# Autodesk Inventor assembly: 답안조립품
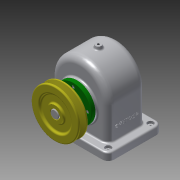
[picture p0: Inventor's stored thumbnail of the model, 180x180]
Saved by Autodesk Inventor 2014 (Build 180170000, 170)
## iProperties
Created: 2016-10
Part Number: 답안조립품
Document SubType Name: Assembly
Designer: USER
Author: USER
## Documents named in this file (15)
- C:\Users\USER\Desktop\461008V1010\답안조립품.iam
- C:\Users\USER\Desktop\461008V1010\V-벨트풀리.ipt
- C:\Users\USER\Desktop\461008V1010\뒤커버.ipt
- C:\Users\USER\Desktop\461008V1010\멈춤나사 - M4x10.ipt
- C:\Users\USER\Desktop\461008V1010\베어링 6203.ipt
- C:\Users\USER\Desktop\461008V1010\본체.ipt
- C:\Users\USER\Desktop\461008V1010\볼트 M3 x 8.ipt
- C:\Users\USER\Desktop\461008V1010\볼트 M3 x 10.ipt
- C:\Users\USER\Desktop\461008V1010\부시.ipt
- C:\Users\USER\Desktop\461008V1010\스퍼기어.ipt
- C:\Users\USER\Desktop\461008V1010\앞커버.ipt
- C:\Users\USER\Desktop\461008V1010\오일씰 28 40 8.ipt
- C:\Users\USER\Desktop\461008V1010\축.ipt
- C:\Users\USER\Desktop\461008V1010\키 - 5 x 5 x 18.ipt
- C:\Users\USER\Desktop\461008V1010\키 - 6 x 6 x 22.ipt
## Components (9 placed, 3 different names)
1. V-벨트풀리:1
2. ISO 4762 M3 x 10:1
3. ISO 4762 M3 x 10:2
4. ISO 4762 M3 x 10:3
5. ISO 4762 M3 x 10:4
6. ISO 4762 M3 x 8:1
7. ISO 4762 M3 x 8:2
8. ISO 4762 M3 x 8:3
9. ISO 4762 M3 x 8:4
